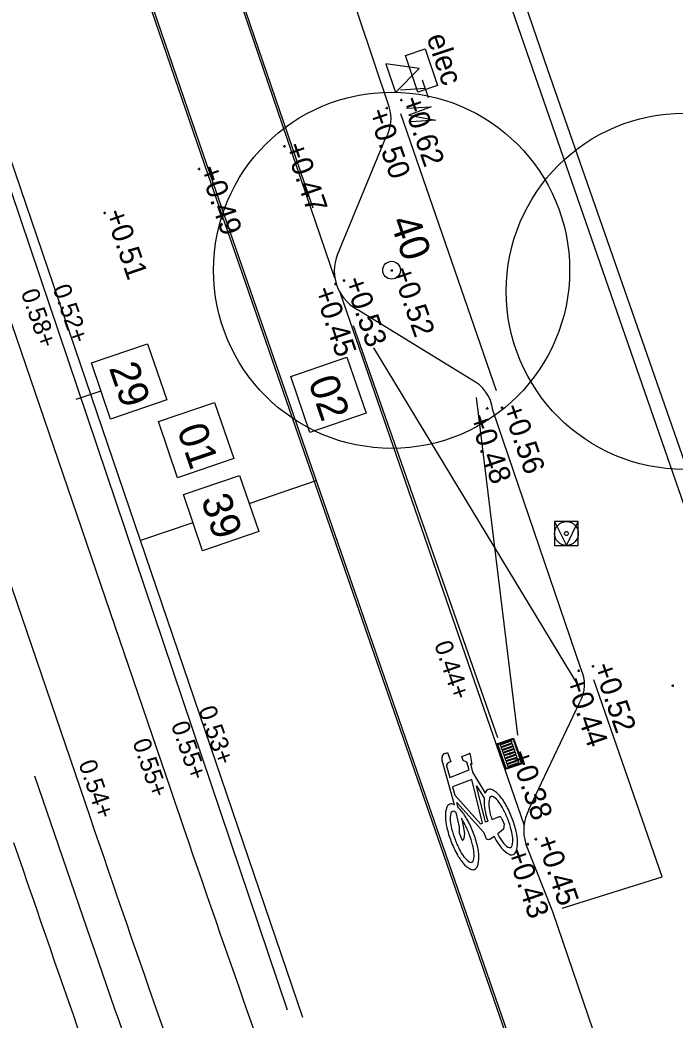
# Model space of a CAD drawing. Extents: x 122462 to 123306, y 485548 to 486417.
# Drawn here: x 122896.03 to 122907.06, y 485918.32 to 485935.16 of the extents above; entities that cross this region are included whole.
import ezdxf

# ---------------------------------------------------------------- set-up
doc = ezdxf.new("R2010")
doc.units = 0
for name, color, linetype in [('B meubilair trammast', 7, 'Continuous'), ('B-WE-GR-BOOM_BOOMDIAMETER-T25', 7, 'Continuous'), ('B-WE-IE-MEUBILAIR_ELECTRAKAST-S', 7, 'Continuous'), ('B-WE-IE-TERREINAFSCHEIDING_KUNSTMATIG_HEKWERK-G', 7, 'Continuous'), ('B-WE-OG-HOOGTEPUNT-S', 7, 'Continuous'), ('B-WE-RI-HWA_KOLK-S', 7, 'Continuous'), ('B-WE-VH-KANTOPSLUITING_OPSLUITBAND_100X200-G', 7, 'Continuous'), ('B-WE-VH-KANTOPSLUITING_TROTTOIRBAND_130 150-G', 7, 'Continuous'), ('B-WE-VH-MATERIAALGRENS_ASFALT-G', 7, 'Continuous'), ('B-WE-VW-MARKERING_LANGS_STREEP_11_010-G', 7, 'Continuous'), ('B-WE-VW-MARKERING_LANGS_STREEP_DOORGETROKKEN_010-G', 7, 'Continuous'), ('B-WE-VW-MARKERING_SYMBOOL-S', 7, 'Continuous'), ('Bestaand Hoogtemaat vast', 7, 'Continuous'), ('iba7-verkeersbord rood', 7, 'Continuous'), ('N tekst', 7, 'Continuous'), ('V markering 1-1 10 cm', 7, 'Continuous'), ('V markering ononderbroken streep 10 cm', 7, 'Continuous'), ('V materiaalscheiding algemeen', 7, 'Continuous'), ('V Rails', 7, 'Continuous'), ('V RWS-band 115-225x250 mm specie', 7, 'Continuous'), ('X-WE-AL-TEKENBLAD-S', 7, 'Continuous')]:
    doc.layers.add(name, color=color, linetype=linetype)

msp = doc.modelspace()

# ---------------------------------------------------------------- linework, layer by layer
at = {"layer": 'B meubilair trammast'}
for p, q in [((122902.754, 485934.339), (122902.193, 485934.42)), ((122902.193, 485934.42), (122902.355, 485933.938)), ((122902.355, 485933.938), (122902.754, 485934.339)), ((122902.807, 485934.15), (122902.907, 485933.85)), ((122902.857, 485934.001), (122902.44, 485933.974)), ((122902.542, 485933.671), (122902.958, 485933.697)), ((122902.958, 485933.697), (122902.581, 485933.556)), ((122902.581, 485933.556), (122903.035, 485933.468)), ((122903.035, 485933.468), (122902.619, 485933.442))]:
    msp.add_line(p, q, dxfattribs=at)
at = {"layer": 'B-WE-IE-MEUBILAIR_ELECTRAKAST-S'}
for p, q in [((122902.526, 485934.559), (122902.857, 485934.67)), ((122902.734, 485933.943), (122902.526, 485934.559)), ((122902.857, 485934.67), (122903.065, 485934.054)), ((122903.065, 485934.054), (122902.734, 485933.943))]:
    msp.add_line(p, q, dxfattribs=at)
at = {"layer": 'B-WE-IE-TERREINAFSCHEIDING_KUNSTMATIG_HEKWERK-G'}
msp.add_lwpolyline([(122913.109, 485920.57), (122912.323, 485922.986), (122909.28, 485921.833), (122904.924, 485934.32), (122900.18, 485948.116), (122898.098, 485954.01)], dxfattribs=at)
at = {"layer": 'B-WE-OG-HOOGTEPUNT-S'}
for p, q in [((122902.434, 485933.809), (122902.474, 485933.809)), ((122902.454, 485933.829), (122902.454, 485933.789)), ((122902.189, 485933.674), (122902.229, 485933.674)), ((122902.209, 485933.694), (122902.209, 485933.654)), ((122900.465, 485933.032), (122900.505, 485933.032)), ((122900.485, 485933.052), (122900.485, 485933.012)), ((122899.026, 485932.65), (122899.066, 485932.65)), ((122899.046, 485932.67), (122899.046, 485932.63)), ((122897.435, 485931.908), (122897.475, 485931.908)), ((122897.455, 485931.928), (122897.455, 485931.888)), ((122902.272, 485930.939), (122902.312, 485930.939)), ((122902.292, 485930.959), (122902.292, 485930.919)), ((122901.323, 485930.713), (122901.363, 485930.713)), ((122901.343, 485930.733), (122901.343, 485930.693)), ((122901.468, 485930.77), (122901.508, 485930.77)), ((122901.488, 485930.79), (122901.488, 485930.75)), ((122903.88, 485928.615), (122903.92, 485928.615)), ((122903.9, 485928.635), (122903.9, 485928.595)), ((122904.13, 485928.63), (122904.17, 485928.63)), ((122904.15, 485928.65), (122904.15, 485928.61)), ((122905.683, 485924.292), (122905.683, 485924.252)), ((122905.421, 485924.198), (122905.461, 485924.198)), ((122905.441, 485924.218), (122905.441, 485924.178)), ((122905.663, 485924.272), (122905.703, 485924.272)), ((122907.007, 485923.947), (122907.047, 485923.947)), ((122907.027, 485923.967), (122907.027, 485923.927)), ((122904.258, 485922.8), (122904.298, 485922.8)), ((122904.278, 485922.82), (122904.278, 485922.78)), ((122904.565, 485921.277), (122904.605, 485921.277)), ((122904.585, 485921.297), (122904.585, 485921.257)), ((122904.7, 485921.361), (122904.74, 485921.361)), ((122904.72, 485921.381), (122904.72, 485921.341))]:
    msp.add_line(p, q, dxfattribs=at)
at = {"layer": 'B-WE-RI-HWA_KOLK-S'}
for p, q in [((122904.062, 485922.964), (122904.346, 485923.062)), ((122904.21, 485922.539), (122904.062, 485922.964)), ((122904.081, 485922.955), (122904.337, 485923.043)), ((122904.219, 485922.558), (122904.081, 485922.955)), ((122904.337, 485923.043), (122904.474, 485922.646)), ((122904.346, 485923.062), (122904.493, 485922.637)), ((122904.21, 485922.539), (122904.493, 485922.637)), ((122904.219, 485922.558), (122904.474, 485922.646))]:
    msp.add_line(p, q, dxfattribs=at)
for points in [[(122904.122, 485922.938), (122904.126, 485922.927)], [(122904.302, 485923.011), (122904.128, 485922.951)], [(122904.139, 485922.92), (122904.313, 485922.981)], [(122904.319, 485922.964), (122904.145, 485922.903)], [(122904.155, 485922.873), (122904.329, 485922.933)], [(122904.319, 485922.993), (122904.315, 485923.005)], [(122904.335, 485922.946), (122904.331, 485922.958)], [(122904.138, 485922.891), (122904.142, 485922.879)], [(122904.155, 485922.843), (122904.159, 485922.832)], [(122904.335, 485922.916), (122904.161, 485922.856)], [(122904.171, 485922.826), (122904.346, 485922.886)], [(122904.171, 485922.796), (122904.175, 485922.785)], [(122904.351, 485922.869), (122904.177, 485922.809)], [(122904.188, 485922.779), (122904.362, 485922.839)], [(122904.368, 485922.822), (122904.194, 485922.762)], [(122904.204, 485922.731), (122904.378, 485922.792)], [(122904.384, 485922.775), (122904.21, 485922.714)], [(122904.352, 485922.899), (122904.348, 485922.91)], [(122904.368, 485922.852), (122904.364, 485922.863)], [(122904.384, 485922.804), (122904.38, 485922.816)], [(122904.401, 485922.757), (122904.397, 485922.769)], [(122904.188, 485922.749), (122904.191, 485922.738)], [(122904.204, 485922.702), (122904.208, 485922.69)], [(122904.22, 485922.654), (122904.224, 485922.643)], [(122904.221, 485922.684), (122904.395, 485922.744)], [(122904.401, 485922.727), (122904.226, 485922.667)], [(122904.237, 485922.637), (122904.411, 485922.697)], [(122904.237, 485922.607), (122904.241, 485922.596)], [(122904.417, 485922.68), (122904.243, 485922.62)], [(122904.253, 485922.59), (122904.427, 485922.65)], [(122904.417, 485922.71), (122904.413, 485922.721)], [(122904.434, 485922.663), (122904.43, 485922.674)]]:
    msp.add_lwpolyline(points, dxfattribs=at)
for centre, start, end in [((122904.131, 485922.941), 109.1123, 199.1123), ((122904.135, 485922.93), 199.1123, 289.1123), ((122904.306, 485923.002), 19.1123, 109.1123), ((122904.309, 485922.99), 289.1123, 19.1123), ((122904.322, 485922.954), 19.1123, 109.1123), ((122904.326, 485922.943), 289.1123, 19.1123), ((122904.148, 485922.894), 109.1123, 199.1123), ((122904.152, 485922.883), 199.1123, 289.1123), ((122904.164, 485922.847), 109.1123, 199.1123), ((122904.168, 485922.835), 199.1123, 289.1123), ((122904.181, 485922.799), 109.1123, 199.1123), ((122904.185, 485922.788), 199.1123, 289.1123), ((122904.197, 485922.752), 109.1123, 199.1123), ((122904.338, 485922.907), 19.1123, 109.1123), ((122904.342, 485922.896), 289.1123, 19.1123), ((122904.355, 485922.86), 19.1123, 109.1123), ((122904.359, 485922.848), 289.1123, 19.1123), ((122904.371, 485922.813), 19.1123, 109.1123), ((122904.375, 485922.801), 289.1123, 19.1123), ((122904.387, 485922.765), 19.1123, 109.1123), ((122904.391, 485922.754), 289.1123, 19.1123), ((122904.201, 485922.741), 199.1123, 289.1123), ((122904.213, 485922.705), 109.1123, 199.1123), ((122904.217, 485922.694), 199.1123, 289.1123), ((122904.23, 485922.658), 109.1123, 199.1123), ((122904.234, 485922.646), 199.1123, 289.1123), ((122904.246, 485922.61), 109.1123, 199.1123), ((122904.25, 485922.599), 199.1123, 289.1123), ((122904.404, 485922.718), 19.1123, 109.1123), ((122904.408, 485922.707), 289.1123, 19.1123), ((122904.42, 485922.671), 19.1123, 109.1123), ((122904.424, 485922.659), 289.1123, 19.1123)]:
    msp.add_arc(centre, 0.01, start, end, dxfattribs=at)
at = {"layer": 'B-WE-VH-KANTOPSLUITING_OPSLUITBAND_100X200-G'}
for points in [[(122913.961, 485923.465), (122909.075, 485921.649), (122904.526, 485934.752), (122901.455, 485943.609), (122897.901, 485953.916)], [(122904.058, 485928.911), (122902.444, 485933.576)], [(122905.164, 485920.198), (122906.847, 485920.728), (122905.695, 485924.046)]]:
    msp.add_lwpolyline(points, dxfattribs=at)
at = {"layer": 'B-WE-VH-KANTOPSLUITING_TROTTOIRBAND_130 150-G'}
for points in [[(122902.25, 485933.693), (122900.962, 485937.531)], [(122901.41, 485931.285), (122902.195, 485933.177)], [(122903.632, 485929.101), (122901.71, 485930.282)], [(122905.48, 485924.235), (122903.996, 485928.588)], [(122904.603, 485921.86), (122905.455, 485923.657)], [(122906.372, 485916.137), (122905.006, 485920.138), (122904.551, 485921.281)]]:
    msp.add_lwpolyline(points, dxfattribs=at)
for centre, radius, start, end in [((122901.638, 485933.497), 0.643, 330.1718, 17.7752), ((122902.072, 485930.936), 0.748, 152.2383, 241.0358), ((122903.342, 485928.511), 0.658, 6.7973, 63.874), ((122904.93, 485923.969), 0.61, 329.3054, 25.8325), ((122905.265, 485921.509), 0.749, 152.0724, 197.7337)]:
    msp.add_arc(centre, radius, start, end, dxfattribs=at)
at = {"layer": 'B-WE-VH-MATERIAALGRENS_ASFALT-G'}
msp.add_line((122904.522, 485921.603), (122901.43, 485930.552), dxfattribs=at)
msp.add_lwpolyline([(122901.335, 485930.807), (122898.446, 485939.272)], dxfattribs=at)
at = {"layer": 'B-WE-VW-MARKERING_LANGS_STREEP_11_010-G'}
for points in [[(122900.966, 485931.989), (122898.927, 485937.963)], [(122904.08, 485923.066), (122901.646, 485930.005)]]:
    msp.add_lwpolyline(points, dxfattribs=at)
at = {"layer": 'B-WE-VW-MARKERING_LANGS_STREEP_DOORGETROKKEN_010-G'}
for points in [[(122901.986, 485929.636), (122905.445, 485923.928)], [(122904.415, 485923.115), (122903.718, 485928.8)]]:
    msp.add_lwpolyline(points, dxfattribs=at)
at = {"layer": 'B-WE-VW-MARKERING_SYMBOOL-S'}
for points in [[(122903.197, 485922.805), (122903.231, 485922.819), (122903.29, 485922.664), (122903.256, 485922.651)], [(122903.213, 485922.596), (122903.269, 485922.401), (122903.598, 485922.527), (122903.558, 485922.658), (122903.498, 485922.685), (122903.472, 485922.754), (122903.592, 485922.799)], [(122903.616, 485922.789), (122903.64, 485922.621), (122903.617, 485922.632), (122903.652, 485922.488), (122903.868, 485922.136)], [(122903.348, 485921.938), (122903.144, 485922.687), (122903.141, 485922.745)], [(122903.911, 485921.664), (122903.874, 485921.65), (122903.72, 485922.259), (122903.851, 485922.052)], [(122903.414, 485921.89), (122903.388, 485921.98), (122903.843, 485921.474), (122903.874, 485921.394)], [(122903.474, 485921.36), (122903.435, 485921.463), (122903.436, 485921.561), (122903.378, 485921.808)], [(122903.465, 485921.712), (122903.485, 485921.639), (122903.517, 485921.454), (122903.509, 485921.373)], [(122903.979, 485921.69), (122904.097, 485921.735)], [(122904.144, 485921.714), (122904.184, 485921.611), (122904.175, 485921.53), (122904.078, 485921.449)], [(122903.945, 485921.363), (122904.016, 485921.409)]]:
    msp.add_lwpolyline(points, dxfattribs=at)
msp.add_lwpolyline([(122903.354, 485922.101), (122903.788, 485921.617), (122903.823, 485921.63), (122903.64, 485922.366), (122903.314, 485922.241)], close=True, dxfattribs=at)
for centre, radius, start, end in [((122903.199, 485922.747), 0.058, 92.4836, 182.4836), ((122903.6, 485922.787), 0.0154, 8.3898, 123.4474), ((122903.279, 485922.589), 0.0666, 110.9186, 173.865), ((122904.303, 485922.002), 0.455, 161.2298, 162.7912), ((122903.949, 485922.122), 0.0814, 110.9186, 161.2298), ((122903.949, 485922.122), 0.0814, 60.6074, 110.9186), ((122903.766, 485921.797), 0.455, 39.889, 60.6074), ((122903.386, 485921.479), 0.95, 29.0222, 39.889), ((122903.298, 485921.873), 0.0814, 110.9186, 161.2298), ((122903.298, 485921.873), 0.0814, 60.6074, 110.9186), ((122903.114, 485921.548), 0.455, 59.0459, 60.6074), ((122904.303, 485922.002), 0.455, 173.7044, 181.9482), ((122904.797, 485922.019), 0.95, 181.9482, 192.8149), ((122904.321, 485921.956), 0.393, 166.8607, 185.2763), ((122904.805, 485922.001), 0.88, 185.2763, 194.303), ((122903.982, 485922.035), 0.0458, 110.9186, 166.8607), ((122903.982, 485922.035), 0.0458, 54.9765, 110.9186), ((122903.783, 485921.751), 0.393, 36.5608, 54.9765), ((122903.392, 485921.461), 0.88, 27.5342, 36.5608), ((122902.725, 485921.113), 1.705, 20.9186, 29.0222), ((122903.651, 485921.753), 0.455, 161.2298, 181.9482), ((122903.669, 485921.707), 0.393, 166.8607, 185.2763), ((122903.331, 485921.786), 0.0458, 110.9186, 166.8607), ((122903.331, 485921.786), 0.0458, 54.9765, 110.9186), ((122903.131, 485921.502), 0.393, 51.1632, 54.9765), ((122903.114, 485921.548), 0.455, 39.889, 48.7915), ((122902.735, 485921.23), 0.95, 29.0222, 39.889), ((122905.534, 485922.186), 1.705, 192.8149, 197.8343), ((122905.538, 485922.188), 1.636, 194.303, 197.7044), ((122902.721, 485921.111), 1.636, 20.9186, 27.5342), ((122904.146, 485921.77), 0.95, 181.9482, 192.8149), ((122904.154, 485921.752), 0.88, 185.2763, 194.303), ((122902.741, 485921.212), 0.88, 27.5342, 34.6153), ((122902.07, 485920.862), 1.636, 20.9186, 27.5342), ((122902.074, 485920.864), 1.705, 20.9186, 29.0222), ((122904.11, 485921.701), 0.0367, 20.9186, 110.9186), ((122902.721, 485921.111), 1.636, 14.303, 20.9186), ((122902.725, 485921.113), 1.705, 12.8149, 20.9186), ((122904.883, 485921.937), 1.705, 192.8149, 200.9186), ((122904.887, 485921.939), 1.636, 194.303, 200.9186), ((122902.07, 485920.862), 1.636, 14.303, 20.9186), ((122902.074, 485920.864), 1.705, 12.8149, 20.9186), ((122905.538, 485922.188), 1.636, 206.8243, 207.5342), ((122904.867, 485921.838), 0.88, 207.5342, 216.5608), ((122903.454, 485921.298), 0.88, 5.2763, 14.303), ((122903.462, 485921.28), 0.95, 1.9482, 12.8149), ((122904.883, 485921.937), 1.705, 200.9186, 209.0222), ((122904.887, 485921.939), 1.636, 200.9186, 207.5342), ((122903.488, 485921.358), 0.0137, 174.3535, 317.4836), ((122903.468, 485921.377), 0.041, 317.4836, 354.3535), ((122902.803, 485921.049), 0.88, 5.2763, 14.303), ((122902.811, 485921.031), 0.95, 1.9482, 12.8149), ((122903.919, 485921.402), 0.0463, 188.7674, 303.0697), ((122905.534, 485922.186), 1.705, 207.1097, 209.0222), ((122904.873, 485921.82), 0.95, 209.0222, 219.889), ((122904.476, 485921.548), 0.393, 216.5608, 234.9765), ((122904.277, 485921.264), 0.0458, 290.9186, 346.8607), ((122903.939, 485921.343), 0.393, 346.8607, 5.2763), ((122903.957, 485921.297), 0.455, 341.2298, 1.9482), ((122904.222, 485921.571), 0.95, 209.0222, 219.889), ((122904.216, 485921.589), 0.88, 207.5342, 216.5608), ((122903.287, 485921.094), 0.393, 346.8607, 5.2763), ((122904.493, 485921.502), 0.455, 219.889, 240.6074), ((122904.277, 485921.264), 0.0458, 234.9765, 290.9186), ((122904.31, 485921.177), 0.0814, 240.6074, 290.9186), ((122904.31, 485921.177), 0.0814, 290.9186, 341.2298), ((122903.842, 485921.253), 0.455, 219.889, 240.6074), ((122903.825, 485921.299), 0.393, 216.5608, 234.9765), ((122903.626, 485921.015), 0.0458, 234.9765, 290.9186), ((122903.626, 485921.015), 0.0458, 290.9186, 346.8607), ((122903.305, 485921.048), 0.455, 341.2298, 1.9482), ((122903.659, 485920.928), 0.0814, 240.6074, 290.9186), ((122903.659, 485920.928), 0.0814, 290.9186, 341.2298)]:
    msp.add_arc(centre, radius, start, end, dxfattribs=at)
at = {"layer": 'iba7-verkeersbord rood'}
for centre, radius in [((122902.29, 485930.943), 3), ((122907.222, 485930.589), 3), ((122902.29, 485930.943), 0.15), ((122902.29, 485930.943), 0.15)]:
    msp.add_circle(centre, radius, dxfattribs=at)
at = {"layer": 'N tekst'}
for points in [[(122905.036, 485926.309), (122905.436, 485926.309), (122905.436, 485926.709), (122905.036, 485926.709)], [(122905.036, 485926.709), (122905.236, 485926.309), (122905.436, 485926.709)]]:
    msp.add_lwpolyline(points, close=True, dxfattribs=at)
for radius in [0.2, 0.0342]:
    msp.add_circle((122905.236, 485926.509), radius, dxfattribs=at)
at = {"layer": 'V markering 1-1 10 cm'}
msp.add_lwpolyline([(122861.268, 486043.255), (122864.477, 486033.82), (122868.105, 486023.234), (122872.215, 486011.133), (122877.675, 485994.999), (122880.312, 485987.313), (122885.038, 485973.513), (122892.674, 485951.631), (122899.173, 485932.732), (122905.905, 485913.305)], dxfattribs=at)
msp.add_arc((123301.543, 486059.577), 427.846, 198.69687, 200.47426, dxfattribs=at)
at = {"layer": 'V markering ononderbroken streep 10 cm'}
msp.add_lwpolyline([(122900.793, 485918.356), (122895.862, 485932.839), (122890.421, 485948.745), (122886.073, 485961.479), (122881.891, 485973.721)], dxfattribs=at)
at = {"layer": 'V materiaalscheiding algemeen'}
msp.add_lwpolyline([(122861.232, 486043.247), (122864.442, 486033.808), (122868.07, 486023.222), (122872.18, 486011.121), (122877.64, 485994.987), (122880.277, 485987.301), (122885.003, 485973.501), (122892.639, 485951.618), (122899.138, 485932.72), (122905.87, 485913.293)], dxfattribs=at)
at = {"layer": 'V Rails'}
for p, q in [((122859.04, 486037.86), (122898.563, 485922.205)), ((122857.682, 486037.396), (122897.205, 485921.741))]:
    msp.add_line(p, q, dxfattribs=at)
for radius, end in [(499.283, 199.72946), (500.718, 199.72865), (502.073, 199.72789), (503.508, 199.72709)]:
    msp.add_arc((123371.02, 486083.659), radius, 198.86698, end, dxfattribs=at)
at = {"layer": 'V RWS-band 115-225x250 mm specie'}
msp.add_lwpolyline([(122881.712, 485973.732), (122885.936, 485961.375), (122890.294, 485948.692), (122895.718, 485932.752), (122900.529, 485918.488)], dxfattribs=at)
at = {"layer": 'X-WE-AL-TEKENBLAD-S'}
for p, q in [((122897.393, 485928.909), (122896.972, 485928.765)), ((122899.89, 485927.014), (122901.02, 485927.401)), ((122898.944, 485926.69), (122898.058, 485926.389))]:
    msp.add_line(p, q, dxfattribs=at)
for points in [[(122898.178, 485929.706), (122898.501, 485928.759), (122897.555, 485928.436), (122897.232, 485929.382)], [(122901.536, 485929.479), (122901.859, 485928.533), (122900.913, 485928.21), (122900.59, 485929.156)], [(122899.308, 485928.718), (122899.631, 485927.771), (122898.685, 485927.448), (122898.361, 485928.394)], [(122899.728, 485927.488), (122900.051, 485926.541), (122899.105, 485926.218), (122898.782, 485927.164)]]:
    msp.add_lwpolyline(points, close=True, dxfattribs=at)

# ---------------------------------------------------------------- texts
at = {"layer": 'B-WE-GR-BOOM_BOOMDIAMETER-T25'}
msp.add_text('40', height=0.5, rotation=288.851, dxfattribs=at).set_placement((122902.258, 485931.77))
at = {"layer": 'B-WE-IE-MEUBILAIR_ELECTRAKAST-S'}
msp.add_text('elec', height=0.36, rotation=288.5573, dxfattribs=at).set_placement((122902.875, 485934.866))
at = {"layer": 'B-WE-OG-HOOGTEPUNT-S'}
for s, rotation, p in [('+0.62', 289, (122902.454, 485933.809)), ('+0.50', 288.851, (122901.886, 485933.604)), ('+0.47', 289, (122900.485, 485933.032)), ('+0.49', 289, (122899.046, 485932.65)), ('+0.51', 289, (122897.455, 485931.908)), ('+0.52', 289, (122902.292, 485930.939)), ('+0.53', 289, (122901.488, 485930.77)), ('+0.45', 288.851, (122900.977, 485930.606)), ('+0.56', 289, (122904.15, 485928.63)), ('+0.48', 288.851, (122903.588, 485928.465)), ('+0.52', 289, (122905.683, 485924.272)), ('+0.44', 288.851, (122905.213, 485924.034)), ('+0.38', 289, (122904.278, 485922.8)), ('+0.45', 289, (122904.72, 485921.361)), ('+0.43', 288.851, (122904.223, 485921.147))]:
    msp.add_text(s, height=0.36, rotation=rotation, dxfattribs=at).set_placement(p)
at = {"layer": 'Bestaand Hoogtemaat vast'}
for s, rotation, p in [('0.52+', 289.2135, (122896.577, 485930.645)), ('0.58+', 289.2135, (122896.039, 485930.57)), ('0.44+', 289.0343, (122903.004, 485924.644)), ('0.53+', 289.2221, (122899.029, 485923.546)), ('0.55+', 289.2221, (122898.57, 485923.289)), ('0.55+', 289.2221, (122897.92, 485922.997)), ('0.54+', 289.2221, (122897.011, 485922.637))]:
    msp.add_text(s, height=0.3, rotation=rotation, dxfattribs=at).set_placement(p)
at = {"layer": 'X-WE-AL-TEKENBLAD-S'}
for s, p in [('29', (122897.524, 485929.299)), ('02', (122900.882, 485929.073)), ('01', (122898.67, 485928.264)), ('39', (122899.074, 485927.082))]:
    msp.add_text(s, height=0.5, rotation=288.867, dxfattribs=at).set_placement(p)

doc.saveas('drawing.dxf')
